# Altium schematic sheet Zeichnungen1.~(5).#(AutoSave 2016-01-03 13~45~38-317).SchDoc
size A4
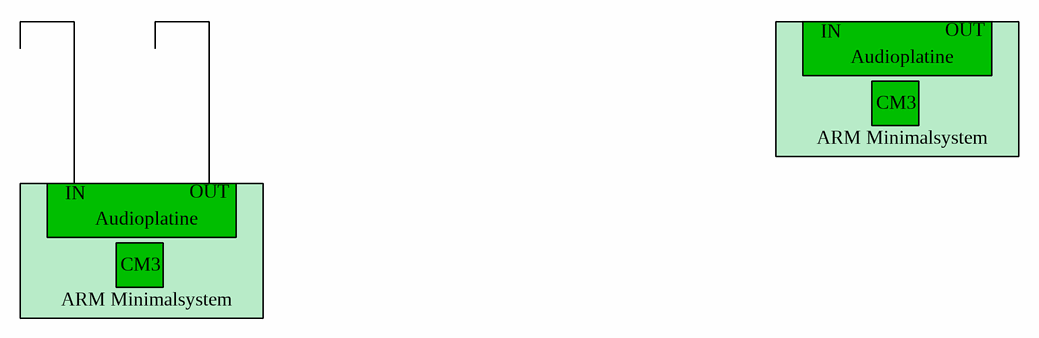
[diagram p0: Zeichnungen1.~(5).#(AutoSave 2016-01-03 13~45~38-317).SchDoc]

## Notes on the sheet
- IN
- Audioplatine
- OUT
- ARM Minimalsystem
- CM3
